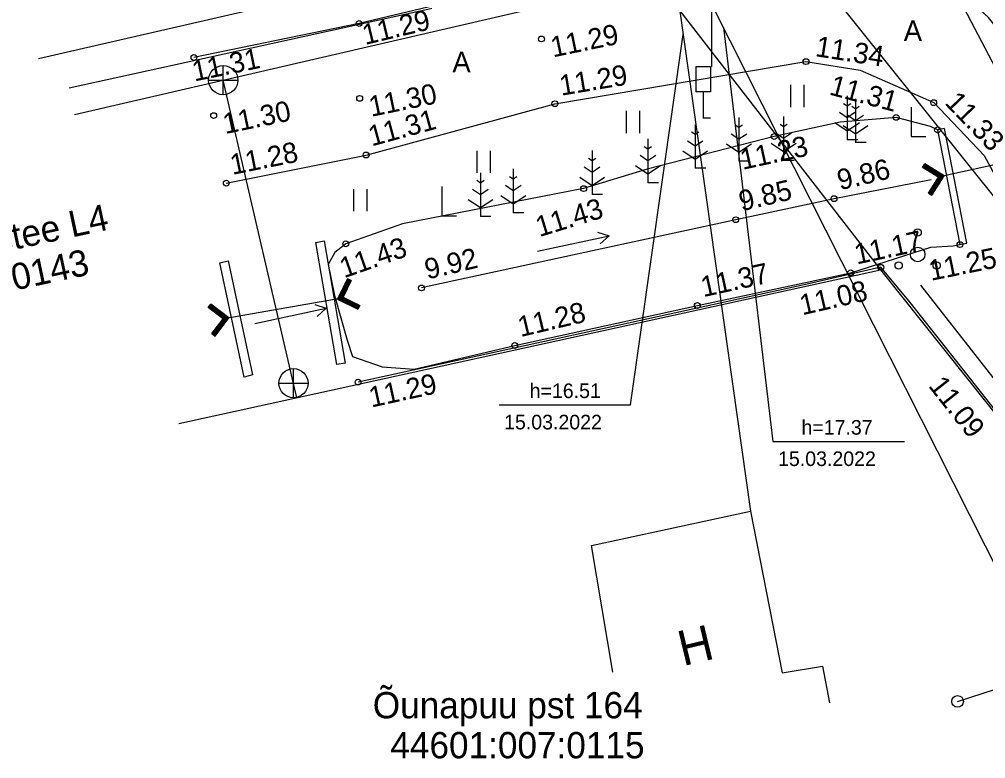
# Model space of a CAD drawing. Extents: x 554198 to 554371, y 6593448 to 6593563.
# Drawn here: x 554226.32 to 554259.39, y 6593474.31 to 6593499.63 of the extents above; entities that cross this region are included whole.
import ezdxf

# ---------------------------------------------------------------- set-up
doc = ezdxf.new("R2010")
doc.units = 0
for name, color, linetype in [('AED', 7, 'Continuous'), ('HALJASTUS', 7, 'Continuous'), ('HOONE', 7, 'Continuous'), ('KKAEV', 7, 'Continuous'), ('KORGUS-EH2000', 7, 'Continuous'), ('KTRASS', 7, 'Continuous'), ('LIIKLUS', 7, 'Continuous'), ('MPOHULIIN', 7, 'Continuous'), ('PIIR', 7, 'Continuous'), ('POST', 7, 'Continuous'), ('PUU', 7, 'Continuous'), ('TEE', 7, 'Continuous'), ('TRUUP', 7, 'Continuous'), ('VEEKOGU', 7, 'Continuous'), ('VORK', 7, 'Continuous'), ('VTRASS', 7, 'Continuous')]:
    doc.layers.add(name, color=color, linetype=linetype)

msp = doc.modelspace()

# ---------------------------------------------------------------- linework, layer by layer
at = {"layer": 'AED'}
msp.add_lwpolyline([(554260.808, 6593479.255), (554260.236, 6593485.581), (554256.809, 6593489.922), (554255.799, 6593491.136), (554253.28, 6593490.558), (554237.91, 6593487.208)], dxfattribs=at)
at = {"layer": 'HALJASTUS'}
for p, q in [((554252.708, 6593497.382), (554252.708, 6593496.621)), ((554253.163, 6593497.382), (554253.163, 6593496.621)), ((554256.841, 6593496.615), (554256.841, 6593495.615)), ((554247.086, 6593496.49), (554247.086, 6593495.729)), ((554247.541, 6593496.49), (554247.541, 6593495.729)), ((554256.841, 6593495.615), (554257.341, 6593495.615)), ((554241.975, 6593495.13), (554241.975, 6593494.369)), ((554242.43, 6593495.13), (554242.43, 6593494.369)), ((554237.753, 6593493.815), (554237.753, 6593493.054)), ((554238.208, 6593493.815), (554238.208, 6593493.054)), ((554240.78, 6593493.903), (554240.78, 6593492.903)), ((554240.78, 6593492.903), (554241.28, 6593492.903))]:
    msp.add_line(p, q, dxfattribs=at)
msp.add_lwpolyline([(554257.157, 6593490.52), (554260.832, 6593485.839), (554261.325, 6593478.347)], dxfattribs=at)
at = {"layer": 'HOONE'}
for points in [[(554246.623, 6593477.281), (554245.894, 6593481.609), (554251.34, 6593482.787), (554252.427, 6593477.253), (554253.8, 6593477.48), (554254.039, 6593476.223)], [(554246.83, 6593476.05), (554246.83, 6593476.05)]]:
    msp.add_lwpolyline(points, dxfattribs=at)
at = {"layer": 'KKAEV'}
for p, q in [((554233.296, 6593497.045), (554233.296, 6593498.045)), ((554232.796, 6593497.545), (554233.796, 6593497.545)), ((554235.7, 6593486.67), (554235.7, 6593487.67)), ((554235.2, 6593487.17), (554236.2, 6593487.17))]:
    msp.add_line(p, q, dxfattribs=at)
for centre in [(554233.296, 6593497.545), (554235.7, 6593487.17)]:
    msp.add_circle(centre, 0.5, dxfattribs=at)
at = {"layer": 'KORGUS-EH2000'}
for centre in [(554237.947, 6593499.485), (554244.185, 6593498.955), (554232.294, 6593498.32), (554253.238, 6593498.179), (554237.965, 6593496.92), (554244.645, 6593496.737), (554257.609, 6593496.774), (554232.968, 6593496.331), (554256.324, 6593496.269), (554257.741, 6593495.842), (554252.15, 6593495.613), (554238.185, 6593494.981), (554233.4, 6593494.02), (554245.63, 6593493.83), (554254.198, 6593493.486), (554250.833, 6593492.766), (554237.49, 6593491.94), (554258.506, 6593491.913), (554254.77, 6593490.95), (554255.799, 6593491.136), (554240.08, 6593490.43), (554249.52, 6593489.83), (554243.27, 6593488.46), (554237.91, 6593487.208)]:
    msp.add_circle(centre, 0.1, dxfattribs=at)
at = {"layer": 'KTRASS'}
for points in [[(554255.375, 6593506.25), (554262.98, 6593491.74)], [(554228.21, 6593496.367), (554251.4, 6593501.74)], [(554235.815, 6593486.673), (554233.296, 6593497.545)]]:
    msp.add_lwpolyline(points, dxfattribs=at)
at = {"layer": 'LIIKLUS'}
for points in [[(554249.468, 6593497.995), (554249.468, 6593497.145)], [(554249.968, 6593497.995), (554249.468, 6593497.995)], [(554249.968, 6593497.995), (554249.968, 6593497.145)], [(554249.968, 6593497.145), (554249.468, 6593497.145)], [(554249.718, 6593497.145), (554249.718, 6593496.245)], [(554249.968, 6593496.245), (554249.718, 6593496.245)]]:
    msp.add_lwpolyline(points, dxfattribs=at)
at = {"layer": 'MPOHULIIN'}
for points in [[(554226.975, 6593498.284), (554248.452, 6593503.231)], [(554248.452, 6593503.231), (554251.34, 6593482.787)], [(554248.452, 6593503.231), (554261.544, 6593477.284)], [(554250.41, 6593499.35), (554252.109, 6593485.174), (554256.608, 6593485.174)], [(554242.736, 6593486.428), (554242.736, 6593486.428), (554247.234, 6593486.428), (554249.034, 6593499.109)]]:
    msp.add_lwpolyline(points, dxfattribs=at)
at = {"layer": 'PIIR'}
for p, q in [((554245.13, 6593504.82), (554255.79, 6593491.05)), ((554231.775, 6593485.788), (554255.79, 6593491.05)), ((554255.79, 6593491.05), (554260.2, 6593485.51))]:
    msp.add_line(p, q, dxfattribs=at)
at = {"layer": 'POST'}
msp.add_line((554258.426, 6593476.274), (554261.544, 6593477.284), dxfattribs=at)
msp.add_circle((554258.426, 6593476.274), 0.2, dxfattribs=at)
at = {"layer": 'PUU'}
for p, q in [((554254.647, 6593497.004), (554254.647, 6593495.504)), ((554254.934, 6593496.904), (554254.934, 6593495.404)), ((554254.647, 6593496.654), (554254.523, 6593496.737)), ((554254.771, 6593496.737), (554254.647, 6593496.654)), ((554254.934, 6593496.554), (554254.81, 6593496.637)), ((554255.058, 6593496.637), (554254.934, 6593496.554)), ((554250.944, 6593496.271), (554250.944, 6593494.771)), ((554252.474, 6593496.297), (554252.474, 6593494.797)), ((554254.647, 6593496.254), (554254.38, 6593496.432)), ((554254.914, 6593496.432), (554254.647, 6593496.254)), ((554254.934, 6593496.154), (554254.667, 6593496.332)), ((554255.201, 6593496.332), (554254.934, 6593496.154)), ((554249.446, 6593496.031), (554249.446, 6593494.531)), ((554250.944, 6593495.921), (554250.82, 6593496.004)), ((554251.068, 6593496.004), (554250.944, 6593495.921)), ((554252.474, 6593495.947), (554252.35, 6593496.03)), ((554252.598, 6593496.03), (554252.474, 6593495.947)), ((554254.223, 6593496.093), (554254.647, 6593495.811)), ((554254.51, 6593495.993), (554254.934, 6593495.711)), ((554254.647, 6593495.811), (554255.071, 6593496.093)), ((554254.934, 6593495.711), (554255.358, 6593495.993)), ((554249.446, 6593495.681), (554249.322, 6593495.764)), ((554249.57, 6593495.764), (554249.446, 6593495.681)), ((554250.944, 6593495.521), (554250.677, 6593495.699)), ((554251.211, 6593495.699), (554250.944, 6593495.521)), ((554252.474, 6593495.547), (554252.207, 6593495.725)), ((554252.741, 6593495.725), (554252.474, 6593495.547)), ((554247.83, 6593495.182), (554247.706, 6593495.265)), ((554247.83, 6593495.532), (554247.83, 6593494.032)), ((554247.954, 6593495.265), (554247.83, 6593495.182)), ((554249.446, 6593495.281), (554249.179, 6593495.459)), ((554249.713, 6593495.459), (554249.446, 6593495.281)), ((554250.52, 6593495.36), (554250.944, 6593495.078)), ((554250.944, 6593495.078), (554251.368, 6593495.36)), ((554252.05, 6593495.386), (554252.474, 6593495.104)), ((554252.474, 6593495.104), (554252.898, 6593495.386)), ((554255.007, 6593495.504), (554254.647, 6593495.504)), ((554255.294, 6593495.404), (554254.934, 6593495.404)), ((554245.918, 6593495.133), (554245.918, 6593493.633)), ((554247.83, 6593494.782), (554247.563, 6593494.96)), ((554248.097, 6593494.96), (554247.83, 6593494.782)), ((554249.022, 6593495.12), (554249.446, 6593494.838)), ((554249.446, 6593494.838), (554249.87, 6593495.12)), ((554245.918, 6593494.783), (554245.794, 6593494.866)), ((554246.042, 6593494.866), (554245.918, 6593494.783)), ((554247.406, 6593494.621), (554247.83, 6593494.339)), ((554247.83, 6593494.339), (554248.254, 6593494.621)), ((554251.304, 6593494.771), (554250.944, 6593494.771)), ((554252.834, 6593494.797), (554252.474, 6593494.797)), ((554242.098, 6593494.372), (554242.098, 6593492.872)), ((554243.222, 6593494.155), (554243.098, 6593494.238)), ((554243.222, 6593494.505), (554243.222, 6593493.005)), ((554243.346, 6593494.238), (554243.222, 6593494.155)), ((554245.918, 6593494.383), (554245.651, 6593494.561)), ((554246.185, 6593494.561), (554245.918, 6593494.383)), ((554249.806, 6593494.531), (554249.446, 6593494.531)), ((554242.098, 6593494.022), (554241.974, 6593494.105)), ((554242.222, 6593494.105), (554242.098, 6593494.022)), ((554243.222, 6593493.755), (554242.955, 6593493.933)), ((554243.489, 6593493.933), (554243.222, 6593493.755)), ((554245.494, 6593494.222), (554245.918, 6593493.94)), ((554245.918, 6593493.94), (554246.342, 6593494.222)), ((554248.19, 6593494.032), (554247.83, 6593494.032)), ((554242.098, 6593493.622), (554241.831, 6593493.8)), ((554242.365, 6593493.8), (554242.098, 6593493.622)), ((554242.798, 6593493.594), (554243.222, 6593493.312)), ((554243.222, 6593493.312), (554243.646, 6593493.594)), ((554246.278, 6593493.633), (554245.918, 6593493.633)), ((554241.674, 6593493.461), (554242.098, 6593493.179)), ((554242.098, 6593493.179), (554242.522, 6593493.461)), ((554243.582, 6593493.005), (554243.222, 6593493.005)), ((554242.458, 6593492.872), (554242.098, 6593492.872))]:
    msp.add_line(p, q, dxfattribs=at)
for centre, radius in [((554257.06, 6593492.326), 0.125), ((554257.06, 6593491.576), 0.25), ((554256.41, 6593491.201), 0.125), ((554257.71, 6593491.201), 0.125)]:
    msp.add_circle(centre, radius, dxfattribs=at)
at = {"layer": 'TEE'}
for points in [[(554265.95, 6593476.82), (554265.59, 6593480.97), (554265.19, 6593483.27), (554264.491, 6593488.567), (554263.957, 6593491.18), (554262.564, 6593494.685), (554261.213, 6593497.518), (554259.482, 6593499.687), (554257.446, 6593501.567), (554254.616, 6593502.167), (554251.838, 6593502.198), (554248.68, 6593501.69), (554243.61, 6593500.842), (554237.947, 6593499.485), (554232.294, 6593498.32)], [(554233.4, 6593494.02), (554238.185, 6593494.981), (554244.645, 6593496.737), (554253.238, 6593498.179), (554255.093, 6593497.886), (554257.609, 6593496.774), (554259.336, 6593494.97), (554261.027, 6593491.848), (554261.746, 6593488.526), (554262.608, 6593483.462), (554262.89, 6593480.7), (554263.27, 6593476.83)]]:
    msp.add_lwpolyline(points, dxfattribs=at)
at = {"layer": 'TRUUP'}
for p, q in [((554257.228, 6593494.557), (554257.304, 6593494.677)), ((554257.233, 6593494.554), (554257.369, 6593494.636)), ((554257.252, 6593494.594), (554257.346, 6593494.651)), ((554257.257, 6593494.539), (554257.393, 6593494.621)), ((554257.865, 6593494.241), (554257.266, 6593494.617)), ((554257.28, 6593494.524), (554257.417, 6593494.606)), ((554257.282, 6593494.641), (554257.322, 6593494.666)), ((554257.963, 6593494.263), (554257.304, 6593494.677)), ((554257.304, 6593494.509), (554257.441, 6593494.592)), ((554257.328, 6593494.494), (554257.464, 6593494.577)), ((554257.767, 6593494.219), (554257.228, 6593494.557)), ((554257.352, 6593494.479), (554257.488, 6593494.562)), ((554257.375, 6593494.464), (554257.512, 6593494.547)), ((554257.399, 6593494.45), (554257.535, 6593494.532)), ((554257.423, 6593494.435), (554257.559, 6593494.517)), ((554257.446, 6593494.42), (554257.583, 6593494.502)), ((554257.47, 6593494.405), (554257.607, 6593494.487)), ((554257.489, 6593493.642), (554257.865, 6593494.241)), ((554257.494, 6593494.39), (554257.63, 6593494.472)), ((554257.518, 6593494.375), (554257.654, 6593494.458)), ((554257.541, 6593494.36), (554257.678, 6593494.443)), ((554257.549, 6593493.604), (554257.963, 6593494.263)), ((554257.565, 6593494.345), (554257.701, 6593494.428)), ((554257.589, 6593494.33), (554257.725, 6593494.413)), ((554257.612, 6593494.316), (554257.749, 6593494.398)), ((554257.636, 6593494.301), (554257.773, 6593494.383)), ((554257.66, 6593494.286), (554257.796, 6593494.368)), ((554257.683, 6593494.271), (554257.82, 6593494.353)), ((554257.694, 6593494.102), (554257.962, 6593494.264)), ((554257.707, 6593494.256), (554257.844, 6593494.338)), ((554257.723, 6593494.149), (554257.938, 6593494.279)), ((554257.731, 6593494.241), (554257.867, 6593494.324)), ((554257.753, 6593494.196), (554257.915, 6593494.294)), ((554257.755, 6593494.226), (554257.891, 6593494.309)), ((554257.429, 6593493.68), (554257.767, 6593494.219)), ((554257.487, 6593493.772), (554257.758, 6593493.936)), ((554257.516, 6593493.819), (554257.787, 6593493.983)), ((554257.546, 6593493.866), (554257.817, 6593494.03)), ((554257.575, 6593493.914), (554257.846, 6593494.077)), ((554257.605, 6593493.961), (554257.876, 6593494.124)), ((554257.634, 6593494.008), (554257.905, 6593494.171)), ((554257.664, 6593494.055), (554257.935, 6593494.218)), ((554257.429, 6593493.68), (554257.549, 6593493.604)), ((554257.43, 6593493.679), (554257.698, 6593493.842)), ((554257.453, 6593493.665), (554257.669, 6593493.795)), ((554257.457, 6593493.725), (554257.728, 6593493.889)), ((554257.477, 6593493.65), (554257.639, 6593493.748)), ((554257.501, 6593493.635), (554257.61, 6593493.701)), ((554257.524, 6593493.62), (554257.58, 6593493.654)), ((554237.548, 6593490.746), (554237.205, 6593490.048)), ((554237.612, 6593490.714), (554237.3, 6593490.08)), ((554237.676, 6593490.683), (554237.395, 6593490.112)), ((554237.652, 6593490.635), (554237.4, 6593490.444)), ((554237.675, 6593490.684), (554237.424, 6593490.494)), ((554237.65, 6593490.696), (554237.449, 6593490.544)), ((554237.625, 6593490.708), (554237.473, 6593490.594)), ((554237.6, 6593490.721), (554237.498, 6593490.644)), ((554237.575, 6593490.733), (554237.523, 6593490.694)), ((554237.676, 6593490.683), (554237.548, 6593490.746)), ((554237.481, 6593490.286), (554237.228, 6593490.095)), ((554237.505, 6593490.336), (554237.253, 6593490.145)), ((554237.53, 6593490.386), (554237.277, 6593490.195)), ((554237.554, 6593490.436), (554237.302, 6593490.245)), ((554237.579, 6593490.485), (554237.326, 6593490.295)), ((554237.603, 6593490.535), (554237.351, 6593490.345)), ((554237.628, 6593490.585), (554237.375, 6593490.394)), ((554237.205, 6593490.048), (554237.903, 6593489.704)), ((554237.456, 6593490.236), (554237.206, 6593490.047)), ((554237.432, 6593490.186), (554237.231, 6593490.035)), ((554237.407, 6593490.137), (554237.256, 6593490.022)), ((554237.408, 6593490.106), (554237.281, 6593490.01)), ((554237.3, 6593490.08), (554237.934, 6593489.768)), ((554237.433, 6593490.094), (554237.306, 6593489.998)), ((554237.459, 6593490.081), (554237.331, 6593489.985)), ((554237.484, 6593490.069), (554237.356, 6593489.973)), ((554237.509, 6593490.057), (554237.382, 6593489.961)), ((554237.395, 6593490.112), (554237.966, 6593489.832)), ((554237.534, 6593490.044), (554237.407, 6593489.948)), ((554237.559, 6593490.032), (554237.432, 6593489.936)), ((554237.584, 6593490.02), (554237.457, 6593489.923)), ((554237.609, 6593490.007), (554237.482, 6593489.911)), ((554237.634, 6593489.995), (554237.507, 6593489.899)), ((554237.659, 6593489.982), (554237.532, 6593489.886)), ((554237.685, 6593489.97), (554237.557, 6593489.874)), ((554237.71, 6593489.958), (554237.583, 6593489.862)), ((554237.735, 6593489.945), (554237.608, 6593489.849)), ((554232.784, 6593489.762), (554232.871, 6593489.875)), ((554233.29, 6593489.376), (554232.784, 6593489.762)), ((554232.789, 6593489.758), (554232.932, 6593489.828)), ((554232.811, 6593489.797), (554232.91, 6593489.845)), ((554232.811, 6593489.741), (554232.954, 6593489.811)), ((554233.39, 6593489.39), (554232.827, 6593489.818)), ((554232.833, 6593489.725), (554232.977, 6593489.794)), ((554232.845, 6593489.841), (554232.888, 6593489.862)), ((554232.856, 6593489.708), (554232.999, 6593489.777)), ((554233.49, 6593489.404), (554232.871, 6593489.875)), ((554232.878, 6593489.691), (554233.021, 6593489.76)), ((554232.9, 6593489.674), (554233.043, 6593489.743)), ((554232.922, 6593489.657), (554233.066, 6593489.726)), ((554232.945, 6593489.64), (554233.088, 6593489.709)), ((554232.967, 6593489.623), (554233.11, 6593489.693)), ((554232.989, 6593489.606), (554233.133, 6593489.676)), ((554233.011, 6593489.589), (554233.155, 6593489.659)), ((554233.034, 6593489.572), (554233.177, 6593489.642)), ((554233.056, 6593489.555), (554233.199, 6593489.625)), ((554233.078, 6593489.538), (554233.222, 6593489.608)), ((554234.378, 6593489.216), (554236.823, 6593489.733)), ((554236.43, 6593489.861), (554236.823, 6593489.733)), ((554236.516, 6593489.457), (554236.823, 6593489.733)), ((554237.76, 6593489.933), (554237.633, 6593489.837)), ((554237.785, 6593489.921), (554237.658, 6593489.825)), ((554237.81, 6593489.908), (554237.683, 6593489.812)), ((554237.835, 6593489.896), (554237.708, 6593489.8)), ((554237.86, 6593489.884), (554237.733, 6593489.788)), ((554237.886, 6593489.871), (554237.758, 6593489.775)), ((554237.911, 6593489.859), (554237.783, 6593489.763)), ((554237.936, 6593489.847), (554237.809, 6593489.75)), ((554237.961, 6593489.834), (554237.834, 6593489.738)), ((554237.946, 6593489.792), (554237.859, 6593489.726)), ((554237.922, 6593489.742), (554237.884, 6593489.713)), ((554237.966, 6593489.832), (554237.903, 6593489.704)), ((554232.905, 6593488.871), (554233.29, 6593489.376)), ((554232.962, 6593488.827), (554233.39, 6593489.39)), ((554233.018, 6593488.784), (554233.49, 6593489.404)), ((554233.101, 6593489.521), (554233.244, 6593489.591)), ((554233.123, 6593489.504), (554233.266, 6593489.574)), ((554233.139, 6593489.178), (554233.424, 6593489.317)), ((554233.145, 6593489.487), (554233.288, 6593489.557)), ((554233.167, 6593489.47), (554233.311, 6593489.54)), ((554233.173, 6593489.223), (554233.457, 6593489.361)), ((554233.19, 6593489.453), (554233.333, 6593489.523)), ((554233.207, 6593489.267), (554233.489, 6593489.404)), ((554233.212, 6593489.436), (554233.355, 6593489.506)), ((554233.234, 6593489.419), (554233.378, 6593489.489)), ((554233.24, 6593489.311), (554233.467, 6593489.421)), ((554233.256, 6593489.402), (554233.4, 6593489.472)), ((554233.274, 6593489.355), (554233.444, 6593489.438)), ((554233.279, 6593489.385), (554233.422, 6593489.455)), ((554232.906, 6593488.87), (554233.188, 6593489.007)), ((554232.928, 6593488.853), (554233.155, 6593488.963)), ((554232.937, 6593488.913), (554233.222, 6593489.052)), ((554232.971, 6593488.957), (554233.255, 6593489.096)), ((554233.005, 6593489.002), (554233.289, 6593489.14)), ((554233.038, 6593489.046), (554233.323, 6593489.184)), ((554233.072, 6593489.09), (554233.356, 6593489.228)), ((554233.106, 6593489.134), (554233.39, 6593489.273)), ((554232.905, 6593488.871), (554233.018, 6593488.784)), ((554232.95, 6593488.836), (554233.121, 6593488.919)), ((554232.973, 6593488.819), (554233.087, 6593488.875)), ((554232.995, 6593488.802), (554233.054, 6593488.831))]:
    msp.add_line(p, q, dxfattribs=at)
msp.add_lwpolyline([(554258.742, 6593491.959), (554257.977, 6593495.888), (554257.741, 6593495.842), (554258.506, 6593491.913)], close=True, dxfattribs=at)
for points in [[(554264.172, 6593495.631), (554257.865, 6593494.241)], [(554236.46, 6593491.99), (554236.75, 6593492.04), (554237.47, 6593487.86), (554237.18, 6593487.81), (554236.46, 6593491.99)], [(554233.18, 6593491.29), (554233.47, 6593491.36), (554234.3, 6593487.45), (554234.01, 6593487.38), (554233.18, 6593491.29)], [(554233.39, 6593489.39), (554237.3, 6593490.08)]]:
    msp.add_lwpolyline(points, dxfattribs=at)
at = {"layer": 'VEEKOGU'}
for p in [(554246.107, 6593492.343), (554244.056, 6593491.69), (554246.194, 6593491.939)]:
    msp.add_line(p, (554246.5, 6593492.216), dxfattribs=at)
for points in [[(554257.741, 6593495.842), (554257.497, 6593495.955), (554256.324, 6593496.269), (554254.409, 6593496.104), (554252.15, 6593495.613), (554247.805, 6593494.493), (554245.63, 6593493.83), (554239.43, 6593492.62), (554237.49, 6593491.94), (554237.11, 6593491.64), (554236.89, 6593491.23), (554237.109, 6593490.17), (554237.54, 6593488.64), (554237.72, 6593488.08), (554238.74, 6593487.73), (554239.83, 6593487.65), (554243.27, 6593488.46), (554249.52, 6593489.83), (554254.77, 6593490.95), (554257.511, 6593491.825), (554258.278, 6593491.867), (554258.506, 6593491.913)], [(554257.527, 6593494.134), (554254.198, 6593493.486), (554250.833, 6593492.766), (554240.08, 6593490.43)]]:
    msp.add_lwpolyline(points, dxfattribs=at)
at = {"layer": 'VORK'}
msp.add_line((554250, 6593502), (554250, 6593498), dxfattribs=at)
at = {"layer": 'VTRASS'}
for points in [[(554260.701, 6593492.276), (554252.41, 6593502.64), (554244.08, 6593513.051)], [(554228.019, 6593497.285), (554252.41, 6593502.64)]]:
    msp.add_lwpolyline(points, dxfattribs=at)

# ---------------------------------------------------------------- texts
at = {"layer": 'HOONE'}
msp.add_text('H', height=1.2, rotation=13.4652, dxfattribs=at).set_placement((554249.029, 6593477.479))
at = {"layer": 'KORGUS-EH2000'}
for s, rotation, p in [(' 11.29 ', 13.4755, (554237.897, 6593498.686)), (' 11.29 ', 11.6448, (554244.326, 6593498.269)), (' 11.34 ', 351.0242, (554253.274, 6593498.409)), (' 11.31 ', 11.6448, (554232.055, 6593497.444)), (' 11.29 ', 9.5261, (554244.606, 6593496.967)), (' 11.31 ', 345.0139, (554253.752, 6593497.126)), (' 11.30 ', 11.6448, (554238.106, 6593496.234)), (' 11.33 ', 313.7508, (554257.778, 6593496.935)), (' 11.30 ', 11.6448, (554233.109, 6593495.645)), (' 11.31 ', 15.2071, (554238.124, 6593495.206)), (' 11.23 ', 12.2627, (554250.816, 6593494.417)), (' 11.28 ', 11.356, (554233.354, 6593494.249)), (' 9.86 ', 13.2498, (554254.145, 6593493.713)), (' 9.85 ', 13.2498, (554250.78, 6593492.993)), (' 11.43 ', 16.9527, (554243.866, 6593492.094)), (' 11.17 ', 12.0426, (554254.721, 6593491.178)), (' 11.43 ', 19.3164, (554237.188, 6593490.673)), (' 9.92 ', 13.2498, (554240.027, 6593490.657)), (' 11.25 ', 11.4066, (554257.261, 6593490.622)), (' 11.37 ', 12.3637, (554249.47, 6593490.058)), (' 11.08 ', 12.9232, (554252.858, 6593489.435)), (' 11.28 ', 13.2498, (554243.217, 6593488.687)), (' 11.29 ', 12.2957, (554238.112, 6593486.28)), (' 11.09 ', 308.2893, (554257.245, 6593487.274))]:
    msp.add_text(s, height=0.7, rotation=rotation, dxfattribs=at).set_placement(p)
at = {"layer": 'MPOHULIIN'}
for s, p in [('h=16.51', (554243.782, 6593486.66)), ('15.03.2022', (554242.908, 6593485.588)), ('h=17.37', (554253.083, 6593485.407)), ('15.03.2022', (554252.282, 6593484.334))]:
    msp.add_text(s, height=0.5, dxfattribs=at).set_placement(p)
at = {"layer": 'PIIR'}
for s, p in [('Õunapuu puiestee L4', (554218.168, 6593490.037)), ('44601:001:0143', (554220.255, 6593489.082))]:
    msp.add_text(s, height=0.9, rotation=12.0272, dxfattribs=at).set_placement(p)
for s, p in [('Õunapuu pst 164', (554238.414, 6593475.696)), ('44601:007:0115', (554239.014, 6593474.327))]:
    msp.add_text(s, height=0.9, dxfattribs=at).set_placement(p)
at = {"layer": 'TEE'}
for p in [(554256.584, 6593498.887), (554241.139, 6593497.814)]:
    msp.add_text('A', height=0.7, dxfattribs=at).set_placement(p)

doc.saveas('drawing.dxf')
